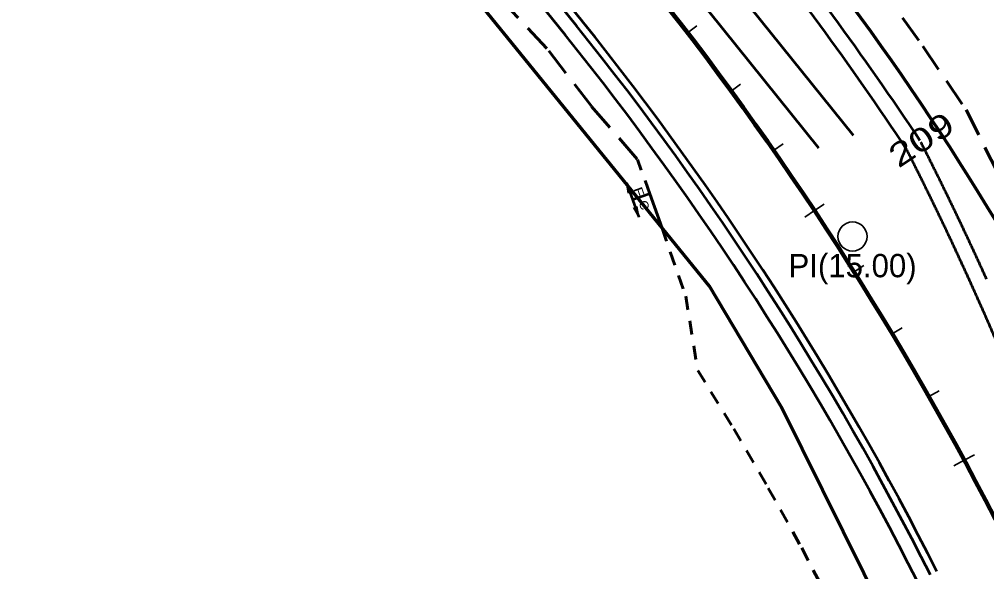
# Model space of a CAD drawing. Extents: x 2717836 to 2719883, y 337327 to 339813.
# Drawn here: x 2718187.5 to 2718519.7, y 338902.6 to 339092.2 of the extents above; entities that cross this region are included whole.
import ezdxf
from ezdxf.enums import TextEntityAlignment as Align

# ---------------------------------------------------------------- set-up
doc = ezdxf.new("R2010")
doc.units = 0
doc.header["$LTSCALE"] = 3.2
for name, pattern in [('LONG_DASHED', [7.5, 6, -1.5]), ('MEDIUM_DASHED', [4.5, 3, -1.5]), ('SHORT_DASHED', [2.7, 1.5, -1.2])]:
    doc.linetypes.add(name, pattern=pattern)
for name, color, linetype, lineweight in [('1', 7, 'Continuous', 106), ('22', 7, 'SHORT_DASHED', 60), ('23', 7, 'Continuous', 70), ('31', 7, 'Continuous', 35), ('4', 7, 'Continuous', 53), ('52', 7, 'Continuous', 53), ('7', 7, 'Continuous', 53)]:
    doc.layers.add(name, color=color, linetype=linetype, lineweight=lineweight)

msp = doc.modelspace()

# ---------------------------------------------------------------- hatches: boundary and pattern name
at = {"layer": '52'}
for points in [[(2718395.987, 339036.124), (2718397.77, 339032.936), (2718396.894, 339033.578), (2718396.61, 339032.522)], [(2718400.195, 339024.353), (2718398.413, 339027.541), (2718399.289, 339026.899), (2718399.573, 339027.956)]]:
    msp.add_hatch(color=256, dxfattribs=at).paths.add_polyline_path(points)

# ---------------------------------------------------------------- linework, layer by layer
at = {"layer": '1'}
msp.add_arc((2717543.972, 338418.37), 1100, 26.79977, 38.81809, dxfattribs=at)
at = {"layer": '22', "linetype": 'MEDIUM_DASHED'}
for p, q in [((2718352.29, 339099.766), (2718369.341, 339081.436)), ((2718369.341, 339081.436), (2718383.993, 339062.353)), ((2718383.993, 339062.353), (2718399.778, 339044.096)), ((2718512.6, 339061.15), (2718524.557, 339037.457))]:
    msp.add_line(p, q, dxfattribs=at)
at = {"layer": '22'}
for p, q in [((2718403.977, 339032.34), (2718399.778, 339044.096)), ((2718408.176, 339020.583), (2718416.302, 338997.247)), ((2718416.302, 338997.247), (2718420.433, 338971.719)), ((2718420.433, 338971.719), (2718432.848, 338951.697)), ((2718432.848, 338951.697), (2718444.684, 338931.329)), ((2718444.684, 338931.329), (2718456.142, 338910.745)), ((2718456.142, 338910.745), (2718467.034, 338889.857))]:
    msp.add_line(p, q, dxfattribs=at)
at = {"layer": '22', "linetype": 'LONG_DASHED'}
msp.add_line((2718408.176, 339020.583), (2718403.977, 339032.34), dxfattribs=at)
at = {"layer": '22', "linetype": 'MEDIUM_DASHED'}
msp.add_lwpolyline([(2718482.392, 339104.5), (2718497.743, 339082.997), (2718512.6, 339061.15)], dxfattribs=at)
at = {"layer": '23'}
msp.add_lwpolyline([(2718625.836, 338603.023), (2718449.262, 338959.135), (2718424.429, 339000.578), (2718281.942, 339176.113)], dxfattribs=at)
msp.add_arc((2717727.191, 338544.436), 928.46, 26.92138, 38.79718, dxfattribs=at)
at = {"layer": '31'}
for p, q in [((2718416.956, 339087.623), (2718420.131, 339090.056)), ((2718431.94, 339067.611), (2718435.169, 339069.972)), ((2718446.464, 339047.264), (2718449.746, 339049.551)), ((2718460.523, 339026.592), (2718463.856, 339028.804)), ((2718460.523, 339026.592), (2718457.19, 339024.381)), ((2718474.109, 339005.606), (2718477.491, 339007.742)), ((2718487.213, 338984.317), (2718490.643, 338986.375)), ((2718499.831, 338962.735), (2718503.307, 338964.715)), ((2718511.955, 338940.873), (2718515.475, 338942.773)), ((2718511.955, 338940.873), (2718508.435, 338938.973))]:
    msp.add_line(p, q, dxfattribs=at)
msp.add_circle((2718473.611, 339017.686), 5, dxfattribs=at)
at = {"layer": '4'}
for p, q in [((2718193.316, 339324.6), (2718380.769, 339091.606)), ((2718401.177, 339142.814), (2718473.847, 339052.489)), ((2718390.451, 339137.002), (2718461.947, 339048.136))]:
    msp.add_line(p, q, dxfattribs=at)
for radius, start in [(1138, 33.56822), (1074, 26.79977)]:
    msp.add_arc((2717543.972, 338418.37), radius, start, 38.81809, dxfattribs=at)
for points in [[(2718514.653, 339000.781), (2718514.363, 339001.423), (2718514.077, 339002.055), (2718513.785, 339002.697), (2718513.498, 339003.329), (2718513.206, 339003.97), (2718512.919, 339004.603), (2718512.625, 339005.243), (2718512.332, 339005.884), (2718512.043, 339006.516), (2718511.748, 339007.157), (2718511.459, 339007.788), (2718511.164, 339008.428), (2718510.873, 339009.06), (2718510.577, 339009.699), (2718510.28, 339010.339), (2718509.989, 339010.97), (2718509.691, 339011.61), (2718509.399, 339012.24), (2718509.101, 339012.879), (2718508.807, 339013.51), (2718508.508, 339014.149), (2718508.214, 339014.779), (2718507.914, 339015.417), (2718507.614, 339016.056), (2718507.318, 339016.685), (2718507.017, 339017.324), (2718506.721, 339017.953), (2718506.419, 339018.591), (2718506.122, 339019.22), (2718505.819, 339019.858), (2718505.516, 339020.495), (2718505.218, 339021.124), (2718504.914, 339021.761), (2718504.614, 339022.389), (2718504.309, 339023.026), (2718504.01, 339023.654), (2718503.704, 339024.291), (2718503.398, 339024.928), (2718503.096, 339025.555), (2718502.789, 339026.191), (2718502.487, 339026.819), (2718502.18, 339027.455), (2718501.877, 339028.082), (2718501.568, 339028.717), (2718501.259, 339029.353), (2718500.955, 339029.979), (2718500.645, 339030.615), (2718500.34, 339031.241), (2718500.029, 339031.876), (2718499.724, 339032.502), (2718499.412, 339033.136), (2718499.1, 339033.771), (2718498.793, 339034.396), (2718498.48, 339035.031), (2718498.173, 339035.656), (2718497.859, 339036.29), (2718497.55, 339036.915), (2718497.236, 339037.548), (2718496.926, 339038.173), (2718496.611, 339038.806), (2718496.295, 339039.439), (2718495.985, 339040.064), (2718495.668, 339040.696), (2718495.357, 339041.32), (2718495.039, 339041.953), (2718494.727, 339042.576), (2718494.409, 339043.209), (2718494.09, 339043.841), (2718493.776, 339044.464), (2718493.457, 339045.096), (2718493.143, 339045.718), (2718492.822, 339046.35), (2718492.186, 339047.604)], [(2718534.835, 338953.223), (2718534.575, 338953.874), (2718534.32, 338954.515), (2718534.06, 338955.166), (2718533.804, 338955.808), (2718533.543, 338956.458), (2718533.286, 338957.1), (2718533.024, 338957.75), (2718532.762, 338958.4), (2718532.504, 338959.041), (2718532.24, 338959.691), (2718531.982, 338960.332), (2718531.717, 338960.982), (2718531.458, 338961.622), (2718531.193, 338962.272), (2718530.927, 338962.921), (2718530.666, 338963.562), (2718530.4, 338964.211), (2718530.138, 338964.851), (2718529.871, 338965.5), (2718529.609, 338966.139), (2718529.341, 338966.788), (2718529.077, 338967.427), (2718528.809, 338968.076), (2718528.539, 338968.724), (2718528.275, 338969.363), (2718528.005, 338970.011), (2718527.739, 338970.65), (2718527.468, 338971.298), (2718527.202, 338971.937), (2718526.93, 338972.584), (2718526.658, 338973.232), (2718526.39, 338973.87), (2718526.117, 338974.517), (2718525.849, 338975.155), (2718525.575, 338975.802), (2718525.306, 338976.44), (2718525.031, 338977.087), (2718524.756, 338977.733), (2718524.486, 338978.371), (2718524.21, 338979.017), (2718523.938, 338979.654), (2718523.661, 338980.3), (2718523.389, 338980.937), (2718523.112, 338981.583), (2718522.833, 338982.229), (2718522.56, 338982.865), (2718522.281, 338983.511), (2718522.007, 338984.147), (2718521.727, 338984.792), (2718521.452, 338985.428), (2718521.171, 338986.073), (2718520.89, 338986.718), (2718520.614, 338987.354), (2718520.332, 338987.998), (2718520.055, 338988.634), (2718519.772, 338989.278), (2718519.494, 338989.913), (2718519.211, 338990.557), (2718518.932, 338991.192), (2718518.648, 338991.836), (2718518.363, 338992.48), (2718518.083, 338993.114), (2718517.797, 338993.757), (2718517.516, 338994.392), (2718517.23, 338995.035), (2718516.948, 338995.669), (2718516.661, 338996.312), (2718516.373, 338996.954), (2718516.09, 338997.588), (2718515.801, 338998.23), (2718515.518, 338998.864), (2718515.228, 338999.506), (2718514.944, 339000.139), (2718514.653, 339000.781)]]:
    msp.add_spline(points, degree=3, dxfattribs=at)
at = {"layer": '52'}
for p, q in [((2718395.987, 339036.124), (2718400.195, 339024.353)), ((2718403.977, 339032.34), (2718398.091, 339030.239))]:
    msp.add_line(p, q, dxfattribs=at)
at = {"layer": '52', "lineweight": 25}
for points in [[(2718395.987, 339036.124), (2718397.77, 339032.936), (2718396.894, 339033.578), (2718396.61, 339032.522)], [(2718400.195, 339024.353), (2718398.413, 339027.541), (2718399.289, 339026.899), (2718399.573, 339027.956)]]:
    msp.add_lwpolyline(points, close=True, dxfattribs=at)
at = {"layer": '7'}
for p, q in [((2718187.473, 339319.899), (2718374.925, 339086.905)), ((2718191.368, 339323.033), (2718378.821, 339090.039))]:
    msp.add_line(p, q, dxfattribs=at)
for radius, start in [(1143.5, 33.56822), (1071.5, 26.79977), (1066.5, 26.79977)]:
    msp.add_arc((2717543.972, 338418.37), radius, start, 38.81809, dxfattribs=at)
msp.add_spline([(2718519.663, 339003.051), (2718519.374, 339003.69), (2718519.086, 339004.325), (2718518.793, 339004.97), (2718518.505, 339005.606), (2718518.211, 339006.25), (2718517.923, 339006.885), (2718517.626, 339007.533), (2718517.333, 339008.173), (2718517.043, 339008.808), (2718516.747, 339009.452), (2718516.456, 339010.086), (2718516.159, 339010.729), (2718515.867, 339011.364), (2718515.568, 339012.011), (2718515.272, 339012.65), (2718514.978, 339013.284), (2718514.68, 339013.926), (2718514.386, 339014.56), (2718514.086, 339015.202), (2718513.791, 339015.836), (2718513.491, 339016.478), (2718513.195, 339017.111), (2718512.892, 339017.757), (2718512.592, 339018.394), (2718512.295, 339019.027), (2718511.992, 339019.668), (2718511.695, 339020.301), (2718511.391, 339020.942), (2718511.093, 339021.574), (2718510.787, 339022.219), (2718510.484, 339022.855), (2718510.184, 339023.487), (2718509.878, 339024.127), (2718509.578, 339024.759), (2718509.271, 339025.399), (2718508.97, 339026.03), (2718508.661, 339026.674), (2718508.355, 339027.309), (2718508.053, 339027.94), (2718507.744, 339028.579), (2718507.441, 339029.21), (2718507.131, 339029.849), (2718506.827, 339030.479), (2718506.515, 339031.122), (2718506.206, 339031.756), (2718505.901, 339032.386), (2718505.589, 339033.024), (2718505.283, 339033.654), (2718504.97, 339034.291), (2718504.663, 339034.921), (2718504.348, 339035.562), (2718504.037, 339036.196), (2718503.728, 339036.824), (2718503.414, 339037.462), (2718503.105, 339038.09), (2718502.789, 339038.727), (2718502.479, 339039.355), (2718502.163, 339039.992), (2718501.852, 339040.619), (2718501.533, 339041.26), (2718501.218, 339041.892), (2718500.906, 339042.519), (2718500.588, 339043.155), (2718500.275, 339043.782), (2718499.956, 339044.418), (2718499.642, 339045.044), (2718499.32, 339045.684), (2718499.002, 339046.315), (2718498.687, 339046.941), (2718498.366, 339047.576), (2718498.05, 339048.202), (2718497.727, 339048.839), (2718497.09, 339050.093)], degree=3, dxfattribs=at)

# ---------------------------------------------------------------- texts
at = {"layer": '31', "width": 1.35}
msp.add_text('209', height=8, rotation=33.568, dxfattribs=at).set_placement((2718489.398, 339040.953))
at = {"layer": '31'}
msp.add_text('PI(15.00)', height=8, dxfattribs=at).set_placement((2718473.612, 339003.686), align=Align.CENTER)
at = {"layer": '52'}
for s, width, p in [('F', 1.5, (2718398.897, 339032.383)), ('C', 1.1, (2718400.617, 339027.956))]:
    msp.add_text(s, height=3, rotation=289.654, dxfattribs=dict(at, width=width)).set_placement(p, align=Align.CENTER)

doc.saveas('drawing.dxf')
